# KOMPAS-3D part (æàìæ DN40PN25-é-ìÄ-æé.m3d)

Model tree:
1. Объединить компоненты:1  (labels: СЕНС DN40PN25-В-НО)
2. Эскиз:1
3. Операция выдавливания:1
     Расстояние 1 = 14
4. Фаска:1
     Угол = 45; Длина 1 = 2; Длина 2 = 2

Referenced files in D:\Савин\!СЕНСОР\3D для заказчика\!Новый перечень\СЕНС\6. СЕНС-В-НО\DN40\: СЕНС DN40PN25-В-НО.a3d
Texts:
  СЕНС DN40PN25-В-НО-СВ
  ООО НПП Сенсор
  СЕНС DN40PN25-В-НО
